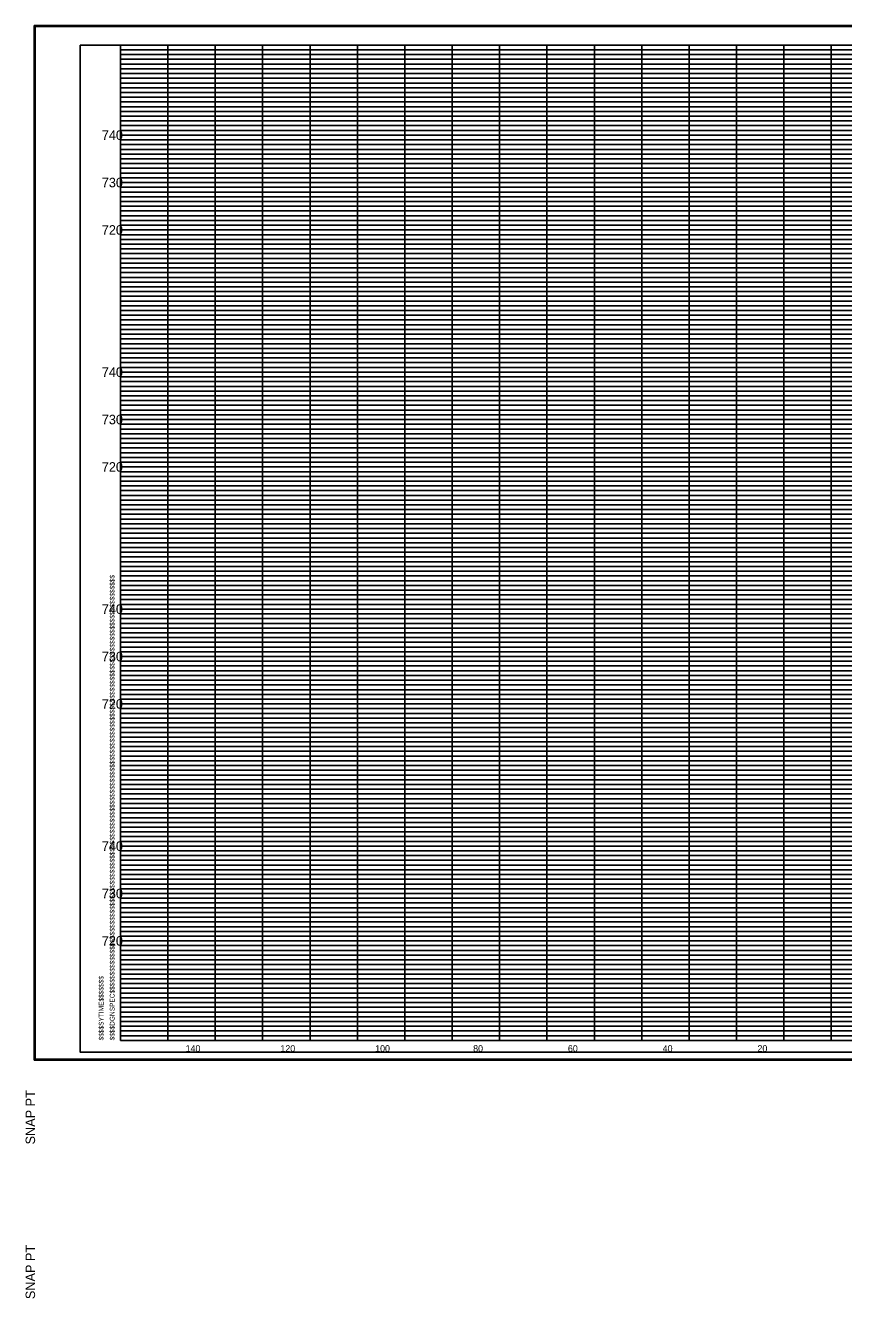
# Model space of a CAD drawing. Extents: x -200 to 1704, y -325 to 2307.
# Drawn here: x 979.9 to 1152.6, y 1485.5 to 1754.1 of the extents above; entities that cross this region are included whole.
import ezdxf

# ---------------------------------------------------------------- set-up
doc = ezdxf.new("R2010")
doc.units = 0
for name, color, linetype in [('DESIGN - SHEET - Corner Text', 7, 'Continuous'), ('DESIGN - SHEET - Light Grid', 7, 'Continuous'), ('DESIGN - SHEET - Linework', 7, 'Continuous'), ('DESIGN - SHEET - Plot Shape', 7, 'Continuous'), ('DESIGN - TYPICAL - Text', 7, 'Continuous')]:
    doc.layers.add(name, color=color, linetype=linetype)

msp = doc.modelspace()

# ---------------------------------------------------------------- linework, layer by layer
at = {"layer": 'DESIGN - SHEET - Light Grid'}
for p, q in [((1000, 1749), (1080, 1749)), ((1080, 1749), (1160, 1749)), ((1000, 1748), (1080, 1748)), ((1000, 1747), (1080, 1747)), ((1000, 1746), (1080, 1746)), ((1080, 1748), (1160, 1748)), ((1080, 1747), (1160, 1747)), ((1080, 1746), (1160, 1746)), ((1000, 1745), (1080, 1745)), ((1000, 1744), (1080, 1744)), ((1080, 1745), (1160, 1745)), ((1080, 1744), (1160, 1744)), ((1000, 1743), (1080, 1743)), ((1000, 1742), (1080, 1742)), ((1000, 1741), (1080, 1741)), ((1080, 1743), (1160, 1743)), ((1080, 1742), (1160, 1742)), ((1080, 1741), (1160, 1741)), ((1000, 1739), (1080, 1739)), ((1000, 1738), (1080, 1738)), ((1080, 1739), (1160, 1739)), ((1080, 1738), (1160, 1738)), ((1000, 1737), (1080, 1737)), ((1000, 1736), (1080, 1736)), ((1080, 1737), (1160, 1737)), ((1080, 1736), (1160, 1736)), ((1000, 1735), (1080, 1735)), ((1000, 1734), (1080, 1734)), ((1000, 1733), (1080, 1733)), ((1080, 1735), (1160, 1735)), ((1080, 1734), (1160, 1734)), ((1080, 1733), (1160, 1733)), ((1000, 1732), (1080, 1732)), ((1000, 1731), (1080, 1731)), ((1080, 1732), (1160, 1732)), ((1080, 1731), (1160, 1731)), ((1000, 1729), (1080, 1729)), ((1000, 1728), (1080, 1728)), ((1080, 1729), (1160, 1729)), ((1080, 1728), (1160, 1728)), ((1000, 1727), (1080, 1727)), ((1000, 1726), (1080, 1726)), ((1000, 1725), (1080, 1725)), ((1080, 1727), (1160, 1727)), ((1080, 1726), (1160, 1726)), ((1080, 1725), (1160, 1725)), ((1000, 1724), (1080, 1724)), ((1000, 1723), (1080, 1723)), ((1000, 1722), (1080, 1722)), ((1080, 1724), (1160, 1724)), ((1080, 1723), (1160, 1723)), ((1080, 1722), (1160, 1722)), ((1000, 1721), (1080, 1721)), ((1000, 1719), (1080, 1719)), ((1080, 1721), (1160, 1721)), ((1080, 1719), (1160, 1719)), ((1000, 1718), (1080, 1718)), ((1000, 1717), (1080, 1717)), ((1080, 1718), (1160, 1718)), ((1080, 1717), (1160, 1717)), ((1000, 1716), (1080, 1716)), ((1000, 1715), (1080, 1715)), ((1000, 1714), (1080, 1714)), ((1080, 1716), (1160, 1716)), ((1080, 1715), (1160, 1715)), ((1080, 1714), (1160, 1714)), ((1000, 1713), (1080, 1713)), ((1000, 1712), (1080, 1712)), ((1000, 1711), (1080, 1711)), ((1080, 1713), (1160, 1713)), ((1080, 1712), (1160, 1712)), ((1080, 1711), (1160, 1711)), ((1000, 1709), (1080, 1709)), ((1080, 1709), (1160, 1709)), ((1000, 1708), (1080, 1708)), ((1000, 1707), (1080, 1707)), ((1000, 1706), (1080, 1706)), ((1080, 1708), (1160, 1708)), ((1080, 1707), (1160, 1707)), ((1080, 1706), (1160, 1706)), ((1000, 1705), (1080, 1705)), ((1000, 1704), (1080, 1704)), ((1000, 1703), (1080, 1703)), ((1080, 1705), (1160, 1705)), ((1080, 1704), (1160, 1704)), ((1080, 1703), (1160, 1703)), ((1000, 1702), (1080, 1702)), ((1000, 1701), (1080, 1701)), ((1080, 1702), (1160, 1702)), ((1080, 1701), (1160, 1701)), ((1000, 1699), (1080, 1699)), ((1000, 1698), (1080, 1698)), ((1080, 1699), (1160, 1699)), ((1080, 1698), (1160, 1698)), ((1000, 1697), (1080, 1697)), ((1000, 1696), (1080, 1696)), ((1000, 1695), (1080, 1695)), ((1080, 1697), (1160, 1697)), ((1080, 1696), (1160, 1696)), ((1080, 1695), (1160, 1695)), ((1000, 1694), (1080, 1694)), ((1000, 1693), (1080, 1693)), ((1080, 1694), (1160, 1694)), ((1080, 1693), (1160, 1693)), ((1000, 1692), (1080, 1692)), ((1000, 1691), (1080, 1691)), ((1080, 1692), (1160, 1692)), ((1080, 1691), (1160, 1691)), ((1000, 1689), (1080, 1689)), ((1000, 1688), (1080, 1688)), ((1000, 1687), (1080, 1687)), ((1080, 1689), (1160, 1689)), ((1080, 1688), (1160, 1688)), ((1080, 1687), (1160, 1687)), ((1000, 1686), (1080, 1686)), ((1000, 1685), (1080, 1685)), ((1080, 1686), (1160, 1686)), ((1080, 1685), (1160, 1685)), ((1000, 1684), (1080, 1684)), ((1000, 1683), (1080, 1683)), ((1000, 1682), (1080, 1682)), ((1080, 1684), (1160, 1684)), ((1080, 1683), (1160, 1683)), ((1080, 1682), (1160, 1682)), ((1000, 1681), (1080, 1681)), ((1000, 1679), (1080, 1679)), ((1080, 1681), (1160, 1681)), ((1080, 1679), (1160, 1679)), ((1000, 1678), (1080, 1678)), ((1000, 1677), (1080, 1677)), ((1080, 1678), (1160, 1678)), ((1080, 1677), (1160, 1677)), ((1000, 1676), (1080, 1676)), ((1000, 1675), (1080, 1675)), ((1000, 1674), (1080, 1674)), ((1080, 1676), (1160, 1676)), ((1080, 1675), (1160, 1675)), ((1080, 1674), (1160, 1674)), ((1000, 1673), (1080, 1673)), ((1000, 1672), (1080, 1672)), ((1000, 1671), (1080, 1671)), ((1080, 1673), (1160, 1673)), ((1080, 1672), (1160, 1672)), ((1080, 1671), (1160, 1671)), ((1000, 1669), (1080, 1669)), ((1000, 1668), (1080, 1668)), ((1080, 1669), (1160, 1669)), ((1080, 1668), (1160, 1668)), ((1000, 1667), (1080, 1667)), ((1000, 1666), (1080, 1666)), ((1080, 1667), (1160, 1667)), ((1080, 1666), (1160, 1666)), ((1000, 1665), (1080, 1665)), ((1000, 1664), (1080, 1664)), ((1000, 1663), (1080, 1663)), ((1080, 1665), (1160, 1665)), ((1080, 1664), (1160, 1664)), ((1080, 1663), (1160, 1663)), ((1000, 1662), (1080, 1662)), ((1000, 1661), (1080, 1661)), ((1080, 1662), (1160, 1662)), ((1080, 1661), (1160, 1661)), ((1000, 1659), (1080, 1659)), ((1000, 1658), (1080, 1658)), ((1080, 1659), (1160, 1659)), ((1080, 1658), (1160, 1658)), ((1000, 1657), (1080, 1657)), ((1000, 1656), (1080, 1656)), ((1000, 1655), (1080, 1655)), ((1080, 1657), (1160, 1657)), ((1080, 1656), (1160, 1656)), ((1080, 1655), (1160, 1655)), ((1000, 1654), (1080, 1654)), ((1000, 1653), (1080, 1653)), ((1000, 1652), (1080, 1652)), ((1080, 1654), (1160, 1654)), ((1080, 1653), (1160, 1653)), ((1080, 1652), (1160, 1652)), ((1000, 1651), (1080, 1651)), ((1080, 1651), (1160, 1651)), ((1000, 1649), (1080, 1649)), ((1000, 1648), (1080, 1648)), ((1000, 1647), (1080, 1647)), ((1080, 1649), (1160, 1649)), ((1080, 1648), (1160, 1648)), ((1080, 1647), (1160, 1647)), ((1000, 1646), (1080, 1646)), ((1000, 1645), (1080, 1645)), ((1000, 1644), (1080, 1644)), ((1080, 1646), (1160, 1646)), ((1080, 1645), (1160, 1645)), ((1080, 1644), (1160, 1644)), ((1000, 1643), (1080, 1643)), ((1000, 1642), (1080, 1642)), ((1080, 1643), (1160, 1643)), ((1080, 1642), (1160, 1642)), ((1000, 1641), (1080, 1641)), ((1000, 1639), (1080, 1639)), ((1080, 1641), (1160, 1641)), ((1080, 1639), (1160, 1639)), ((1000, 1638), (1080, 1638)), ((1000, 1637), (1080, 1637)), ((1000, 1636), (1080, 1636)), ((1080, 1638), (1160, 1638)), ((1080, 1637), (1160, 1637)), ((1080, 1636), (1160, 1636)), ((1000, 1635), (1080, 1635)), ((1000, 1634), (1080, 1634)), ((1080, 1635), (1160, 1635)), ((1080, 1634), (1160, 1634)), ((1000, 1633), (1080, 1633)), ((1000, 1632), (1080, 1632)), ((1000, 1631), (1080, 1631)), ((1080, 1633), (1160, 1633)), ((1080, 1632), (1160, 1632)), ((1080, 1631), (1160, 1631)), ((1000, 1629), (1080, 1629)), ((1000, 1628), (1080, 1628)), ((1080, 1629), (1160, 1629)), ((1080, 1628), (1160, 1628)), ((1000, 1627), (1080, 1627)), ((1000, 1626), (1080, 1626)), ((1000, 1625), (1080, 1625)), ((1080, 1627), (1160, 1627)), ((1080, 1626), (1160, 1626)), ((1080, 1625), (1160, 1625)), ((1000, 1624), (1080, 1624)), ((1000, 1623), (1080, 1623)), ((1080, 1624), (1160, 1624)), ((1080, 1623), (1160, 1623)), ((1000, 1622), (1080, 1622)), ((1000, 1621), (1080, 1621)), ((1080, 1622), (1160, 1622)), ((1080, 1621), (1160, 1621)), ((1000, 1619), (1080, 1619)), ((1000, 1618), (1080, 1618)), ((1000, 1617), (1080, 1617)), ((1080, 1619), (1160, 1619)), ((1080, 1618), (1160, 1618)), ((1080, 1617), (1160, 1617)), ((1000, 1616), (1080, 1616)), ((1000, 1615), (1080, 1615)), ((1080, 1616), (1160, 1616)), ((1080, 1615), (1160, 1615)), ((1000, 1614), (1080, 1614)), ((1000, 1613), (1080, 1613)), ((1000, 1612), (1080, 1612)), ((1080, 1614), (1160, 1614)), ((1080, 1613), (1160, 1613)), ((1080, 1612), (1160, 1612)), ((1000, 1611), (1080, 1611)), ((1000, 1609), (1080, 1609)), ((1080, 1611), (1160, 1611)), ((1080, 1609), (1160, 1609)), ((1000, 1608), (1080, 1608)), ((1000, 1607), (1080, 1607)), ((1080, 1608), (1160, 1608)), ((1080, 1607), (1160, 1607)), ((1000, 1606), (1080, 1606)), ((1000, 1605), (1080, 1605)), ((1000, 1604), (1080, 1604)), ((1080, 1606), (1160, 1606)), ((1080, 1605), (1160, 1605)), ((1080, 1604), (1160, 1604)), ((1000, 1603), (1080, 1603)), ((1000, 1602), (1080, 1602)), ((1000, 1601), (1080, 1601)), ((1080, 1603), (1160, 1603)), ((1080, 1602), (1160, 1602)), ((1080, 1601), (1160, 1601)), ((1000, 1599), (1080, 1599)), ((1080, 1599), (1160, 1599)), ((1000, 1598), (1080, 1598)), ((1000, 1597), (1080, 1597)), ((1000, 1596), (1080, 1596)), ((1080, 1598), (1160, 1598)), ((1080, 1597), (1160, 1597)), ((1080, 1596), (1160, 1596)), ((1000, 1595), (1080, 1595)), ((1000, 1594), (1080, 1594)), ((1000, 1593), (1080, 1593)), ((1080, 1595), (1160, 1595)), ((1080, 1594), (1160, 1594)), ((1080, 1593), (1160, 1593)), ((1000, 1592), (1080, 1592)), ((1000, 1591), (1080, 1591)), ((1080, 1592), (1160, 1592)), ((1080, 1591), (1160, 1591)), ((1000, 1589), (1080, 1589)), ((1000, 1588), (1080, 1588)), ((1080, 1589), (1160, 1589)), ((1080, 1588), (1160, 1588)), ((1000, 1587), (1080, 1587)), ((1000, 1586), (1080, 1586)), ((1000, 1585), (1080, 1585)), ((1080, 1587), (1160, 1587)), ((1080, 1586), (1160, 1586)), ((1080, 1585), (1160, 1585)), ((1000, 1584), (1080, 1584)), ((1000, 1583), (1080, 1583)), ((1080, 1584), (1160, 1584)), ((1080, 1583), (1160, 1583)), ((1000, 1582), (1080, 1582)), ((1000, 1581), (1080, 1581)), ((1080, 1582), (1160, 1582)), ((1080, 1581), (1160, 1581)), ((1000, 1579), (1080, 1579)), ((1000, 1578), (1080, 1578)), ((1000, 1577), (1080, 1577)), ((1080, 1579), (1160, 1579)), ((1080, 1578), (1160, 1578)), ((1080, 1577), (1160, 1577)), ((1000, 1576), (1080, 1576)), ((1000, 1575), (1080, 1575)), ((1000, 1574), (1080, 1574)), ((1080, 1576), (1160, 1576)), ((1080, 1575), (1160, 1575)), ((1080, 1574), (1160, 1574)), ((1000, 1573), (1080, 1573)), ((1000, 1572), (1080, 1572)), ((1080, 1573), (1160, 1573)), ((1080, 1572), (1160, 1572)), ((1000, 1571), (1080, 1571)), ((1000, 1569), (1080, 1569)), ((1080, 1571), (1160, 1571)), ((1080, 1569), (1160, 1569)), ((1000, 1568), (1080, 1568)), ((1000, 1567), (1080, 1567)), ((1000, 1566), (1080, 1566)), ((1080, 1568), (1160, 1568)), ((1080, 1567), (1160, 1567)), ((1080, 1566), (1160, 1566)), ((1000, 1565), (1080, 1565)), ((1000, 1564), (1080, 1564)), ((1080, 1565), (1160, 1565)), ((1080, 1564), (1160, 1564)), ((1000, 1563), (1080, 1563)), ((1000, 1562), (1080, 1562)), ((1000, 1561), (1080, 1561)), ((1080, 1563), (1160, 1563)), ((1080, 1562), (1160, 1562)), ((1080, 1561), (1160, 1561)), ((1000, 1559), (1080, 1559)), ((1000, 1558), (1080, 1558)), ((1080, 1559), (1160, 1559)), ((1080, 1558), (1160, 1558)), ((1000, 1557), (1080, 1557)), ((1000, 1556), (1080, 1556)), ((1080, 1557), (1160, 1557)), ((1080, 1556), (1160, 1556)), ((1000, 1555), (1080, 1555)), ((1000, 1554), (1080, 1554)), ((1000, 1553), (1080, 1553)), ((1080, 1555), (1160, 1555)), ((1080, 1554), (1160, 1554)), ((1080, 1553), (1160, 1553)), ((1000, 1552), (1080, 1552)), ((1000, 1551), (1080, 1551)), ((1080, 1552), (1160, 1552)), ((1080, 1551), (1160, 1551)), ((1000, 1549), (1080, 1549)), ((1000, 1548), (1080, 1548)), ((1080, 1549), (1160, 1549)), ((1080, 1548), (1160, 1548)), ((1000, 1547), (1080, 1547)), ((1000, 1546), (1080, 1546)), ((1000, 1545), (1080, 1545)), ((1080, 1547), (1160, 1547)), ((1080, 1546), (1160, 1546)), ((1080, 1545), (1160, 1545)), ((1000, 1544), (1080, 1544)), ((1000, 1543), (1080, 1543)), ((1000, 1542), (1080, 1542)), ((1080, 1544), (1160, 1544)), ((1080, 1543), (1160, 1543)), ((1080, 1542), (1160, 1542)), ((1000, 1541), (1080, 1541)), ((1080, 1541), (1160, 1541))]:
    msp.add_line(p, q, dxfattribs=at)
at = {"layer": 'DESIGN - SHEET - Linework'}
for p, q in [((981.77, 1535.86), (981.77, 1754.14)), ((981.77, 1754.14), (1322.17, 1754.14)), ((1010, 1540), (1010, 1750)), ((1020, 1540), (1020, 1750)), ((1030, 1540), (1030, 1750)), ((1040, 1540), (1040, 1750)), ((1050, 1540), (1050, 1750)), ((1060, 1540), (1060, 1750)), ((1070, 1540), (1070, 1750)), ((1080, 1540), (1080, 1750)), ((1090, 1540), (1090, 1750)), ((1100, 1540), (1100, 1750)), ((1110, 1540), (1110, 1750)), ((1120, 1540), (1120, 1750)), ((1130, 1540), (1130, 1750)), ((1140, 1540), (1140, 1750)), ((1150, 1540), (1150, 1750)), ((1000, 1740), (1280, 1740)), ((1000, 1730), (1320, 1730)), ((1000, 1720), (1320, 1720)), ((1000, 1710), (1320, 1710)), ((1000, 1700), (1320, 1700)), ((1000, 1690), (1320, 1690)), ((1000, 1680), (1320, 1680)), ((1000, 1670), (1320, 1670)), ((1000, 1660), (1320, 1660)), ((1000, 1650), (1320, 1650)), ((1000, 1640), (1320, 1640)), ((1000, 1630), (1320, 1630)), ((1000, 1620), (1320, 1620)), ((1000, 1610), (1320, 1610)), ((1000, 1600), (1320, 1600)), ((1000, 1590), (1320, 1590)), ((1000, 1580), (1320, 1580)), ((1000, 1570), (1320, 1570)), ((1000, 1560), (1320, 1560)), ((1000, 1550), (1320, 1550)), ((981.77, 1535.86), (1322.17, 1535.86))]:
    msp.add_line(p, q, dxfattribs=at)
msp.add_lwpolyline([(1000, 1750), (1000, 1540), (1320, 1540), (1320, 1750), (1000, 1750)], dxfattribs=at)
at = {"layer": 'DESIGN - SHEET - Plot Shape'}
for points in [[(981.97, 1753.94), (1321.97, 1753.94), (1321.97, 1536.06), (981.97, 1536.06)], [(991.5, 1750), (1320, 1750), (1320, 1537.5), (991.5, 1537.5)]]:
    msp.add_lwpolyline(points, close=True, dxfattribs=at)

# ---------------------------------------------------------------- texts
at = {"layer": 'DESIGN - SHEET - Corner Text'}
for s, height, p in [('$$$$DGNSPEC$$$$$$$$$$$$$$$$$$$$$$$$$$$$$$$$$$$$$$$$$$$$$$$$$$$$$$$$$$$$$$$$$$$$$$$$$$$$$$$$$$$$$$$$$$$$$$$$$$$$$$$$$$$$$$$$$$$', 1.00002, (998.74, 1540)), ('$$$$SYTIME$$$$$$$', 1, (996.42, 1540)), ('SNAP PT  ', 2, (981.97, 1518.06)), ('  SNAP PT', 2, (981.97, 1483.94))]:
    msp.add_text(s, height=height, rotation=90, dxfattribs=at).set_placement(p)
at = {"layer": 'DESIGN - TYPICAL - Text'}
for s, height, p in [('     740     ', 2, (992.34, 1730)), ('     730     ', 2, (992.34, 1720)), ('     720     ', 2, (992.34, 1710)), ('     740     ', 2, (992.34, 1680)), ('     730     ', 2, (992.34, 1670)), ('     720     ', 2, (992.34, 1660)), ('     740     ', 2, (992.34, 1630)), ('     730     ', 2, (992.34, 1620)), ('     720     ', 2, (992.34, 1610)), ('     740     ', 2, (992.34, 1580)), ('     730     ', 2, (992.34, 1570)), ('     720     ', 2, (992.34, 1560)), ('     140     ', 1.4, (1011.14, 1537.6)), ('     120     ', 1.4, (1031.14, 1537.6)), ('     100     ', 1.4, (1051.14, 1537.6)), ('     80     ', 1.4, (1071.82, 1537.6)), ('     60     ', 1.4, (1091.82, 1537.6)), ('     40     ', 1.4, (1111.82, 1537.6)), ('     20     ', 1.4, (1131.82, 1537.6))]:
    msp.add_text(s, height=height, dxfattribs=at).set_placement(p)

doc.saveas('drawing.dxf')
